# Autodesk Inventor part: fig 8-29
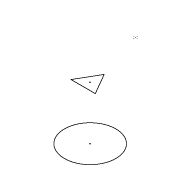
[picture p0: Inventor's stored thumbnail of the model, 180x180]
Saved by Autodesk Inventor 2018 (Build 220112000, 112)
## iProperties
Shininess: 77.0
Angle Display Precision: 2
Document Length Units: 11269
Document Angle Units: 11279
Document Time Units: 11290
Document Mass Units: 11283
Document Length Units Precision: 3
Document Angle Units Precision: 2
Created: 2001-12
Part Number: fig 8-29
Document SubType Name: Modeling
Designer: CADSoft
Density: 1 g/cm^3
Material: Generic
Appearance: Default
Density: 0.0
Volumn: 0.0
Area: 0.0
PropertySet Name: Model Information
Control State: 0
Master: False
Checked Out: False
Author: CADSoft
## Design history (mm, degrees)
workplane "Work Plane3"
workplane "Work Plane4"
sketch "Sketch12"
  geometry: L1 (0, 10.598)-(9.178, -5.299); L2 (9.178, -5.299)-(-9.178, -5.299); L3 (-9.178, -5.299)-(0, 10.598); 1 further point
  constraints: 6 end point, 5 other
workplane "Work Plane5"
body "Solid1"
sketch "Sketch1"
  geometry: C1 r 19.387 at (0, 0); 1 further point
  constraints: 1 centre point, 1 coincident, 1 other
sketch "Sketch2"
  geometry: 1 further point
